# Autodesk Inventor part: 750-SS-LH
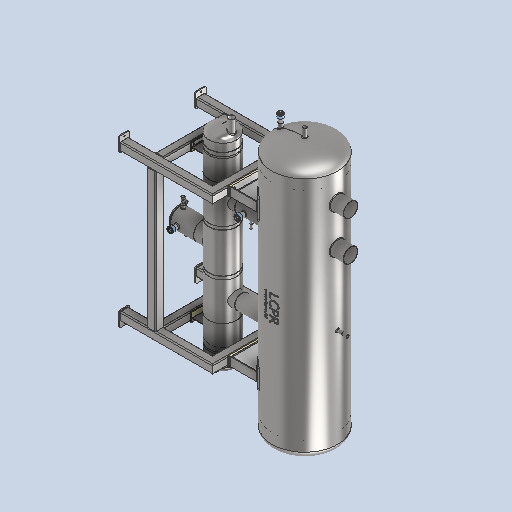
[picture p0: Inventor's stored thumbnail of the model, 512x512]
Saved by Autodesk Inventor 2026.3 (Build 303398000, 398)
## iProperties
Created: 2026-05
Part Number: 750-SS-LH
Material: Generic
Document SubType Name: Modeling
Designer: rva
Density: 1 g/cm^3
Appearance: Default
Author: rva
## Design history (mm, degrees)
derived "LCPR-750-SS-LH.iam"
body "Solid1"
node "LCPR-SS-750-2500-150-WELD.iam:1::750 mm-SS-Dome End Cap.ipt:"
node "LCPR-SS-750-2500-150-WELD.iam:1::750 mm-SS-Dome End Cap.ipt:"
node "LCPR-SS-750-2500-150-WELD.iam:1::H1100-R.ipt:1"
node "LCPR-SS-750-2500-150-WELD.iam:1::LCPR-750-SS-Leg-WELD.iam:1:"
node "LCPR-SS-750-2500-150-WELD.iam:1::LCPR-750-SS-Leg-WELD.iam:2:"
node "LCPR-SS-750-2500-150-WELD.iam:1::LCPR-LOGO.ipt:1"
node "LCPR-SS-750-2500-150-WELD.iam:1::Welds"
node "Sub-SS-300-150-1940-110-75-65.iam:1::ISO 5251 Reducing Tee D"
node "Sub-SS-300-150-1940-110-75-65.iam:1::300-110-SS-Hole Sub Coo"
node "Sub-SS-300-150-1940-110-75-65.iam:1::300-110-SS-Hole Sub Coo"
node "Sub-SS-300-150-1940-110-75-65.iam:1::300 mm-SS-Subcooler Leg"
node "Sub-SS-300-150-1940-110-75-65.iam:1::300 mm-SS-Subcooler Leg"
node "Sub-SS-300-150-1940-110-75-65.iam:1::H1100-R.ipt:2"
node "Sub-SS-300-150-1940-110-75-65.iam:1::ISO 5251 Reducing Tee D"
node "Sub-SS-300-150-1940-110-75-65.iam:1::1-2 Inch NPT Socket - S"
node "Sub-SS-300-150-1940-110-75-65.iam:1::Welds"
node "Sub-SS-300-150-1940-110-75-65.iam:1::200 mm Oil Pot Assembly"
node "LPR-750-Frame Assembly.iam:1::LCPR-SS-750-170 x 120 Frame Fo"
node "LPR-750-Frame Assembly.iam:1::LCPR-SS-750-170 x 120 Frame Fo"
node "LPR-750-Frame Assembly.iam:1::LCPR-SS-750-170 x 120 Frame Fo"
node "LPR-750-Frame Assembly.iam:1::LCPR-SS-750-170 x 120 Frame Fo"
node "Nylon Heat Tranfer Spacer 640x100.ipt:1"
node "Nylon Heat Tranfer Spacer 640x100.ipt:2"
node "AS 1111 - M12 x 140.ipt:1"
node "AS 1112 (4) - Metric M12:1"
node "AS 1237 (4.2) 12 mm:1"
node "AS 1237 (4.2) 12 mm:2"
node "AS 1111 - M12 x 140.ipt:2"
node "AS 1112 (4) - Metric M12:2"
node "AS 1237 (4.2) 12 mm:3"
node "AS 1237 (4.2) 12 mm:4"
node "AS 1111 - M12 x 140.ipt:3"
node "AS 1112 (4) - Metric M12:3"
node "AS 1237 (4.2) 12 mm:5"
node "AS 1237 (4.2) 12 mm:6"
node "AS 1111 - M12 x 140.ipt:4"
node "AS 1112 (4) - Metric M12:4"
node "AS 1237 (4.2) 12 mm:7"
node "AS 1237 (4.2) 12 mm:8"
node "Welds"
node "Nylon Heat Tranfer Spacer 175x100.ipt:1"
node "Nylon Heat Tranfer Spacer 175x100.ipt:2"
node "LCPR-750-SS-LH.iam_Bodies"
